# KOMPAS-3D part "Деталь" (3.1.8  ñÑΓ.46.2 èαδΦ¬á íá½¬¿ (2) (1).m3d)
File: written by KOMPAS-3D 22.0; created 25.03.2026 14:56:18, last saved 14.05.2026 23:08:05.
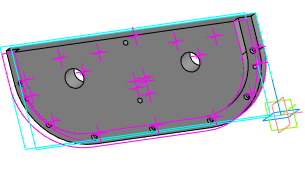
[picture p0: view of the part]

Document properties: Автор: TMK; Полное имя файла: E:\test_kompas\all_v20\3.1.8  дет.46.2 Крышка балки (2) (1).m3d; Организация: TMK

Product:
- Part/product: Деталь
    Масса: 21.934157

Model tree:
1. Операция без истории:1
2. Эскиз:1
3. Смещенная плоскость:1  (with: Операция без истории:1)
4. Эскиз:2
5. Смещенная плоскость:2  (with: Операция без истории:1)
6. Эскиз:3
